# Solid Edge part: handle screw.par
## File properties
Title: Handle Screw
Author: Robert a Rhodes jr
Template: Normal.par
Last saved by: Cadcim
Revision: 9
Application: Solid Edge
Material: aluminum
Accuracy: 0.99
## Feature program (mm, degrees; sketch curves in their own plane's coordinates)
sketch for "unnamed Protrusion 1" plane through (0, 0, 0) normal (0, -1, 0) x-axis (1, 0, 0)
  circle centre (0, 0) radius 7.5
extrude "unnamed Protrusion 1" add finite 14 along +normal
sketch for "Hole_1" plane through (0, -14, 0) normal (0, -1, 0) x-axis (1, 0, 0)
  hole centre (0, 0) bore radius 4
hole "Hole_1" diameter 8 finite  VBottomAngle = 120 deg
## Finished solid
Body 1: solid body, 5 faces, 4 edges, 1 vertex.
  Faces by surface: cylinder 2, plane 2, cone 1
  Edges by curve: circle 4
Bounding box of the edges (mm): 15.000 x 14.000 x 15.000, from (-7.5, -14, -7.5) to (7.5, 0, 7.5).
Cylindrical faces by radius (mm): R4 x1, R7.5 x1
Conical faces (half-angle, radius in mm at the cone's reference point): 60 deg R4 x1
Planar faces by outward normal: +y 1, -y 1
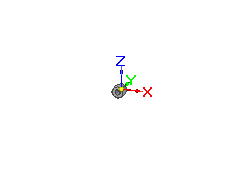
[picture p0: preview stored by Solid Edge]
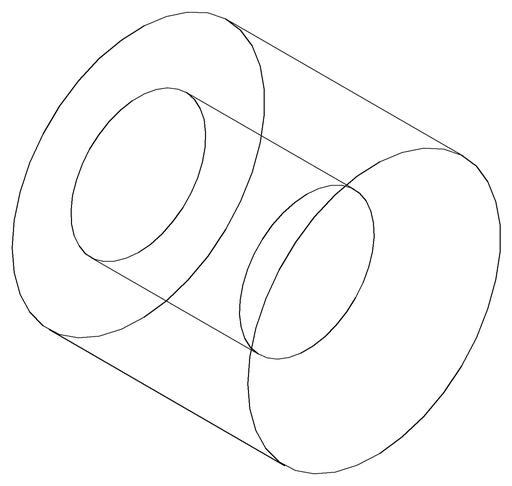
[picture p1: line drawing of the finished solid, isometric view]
